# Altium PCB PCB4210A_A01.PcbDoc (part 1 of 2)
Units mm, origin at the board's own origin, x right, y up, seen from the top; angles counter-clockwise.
Board outline 30 x 45 mm, 4 copper layers (Top Layer, Signal Layer 2, Signal Layer 3, Bottom Layer), stack 1.6 mm thick; 78 components, 78 nets, 297 pads, 463 vias.
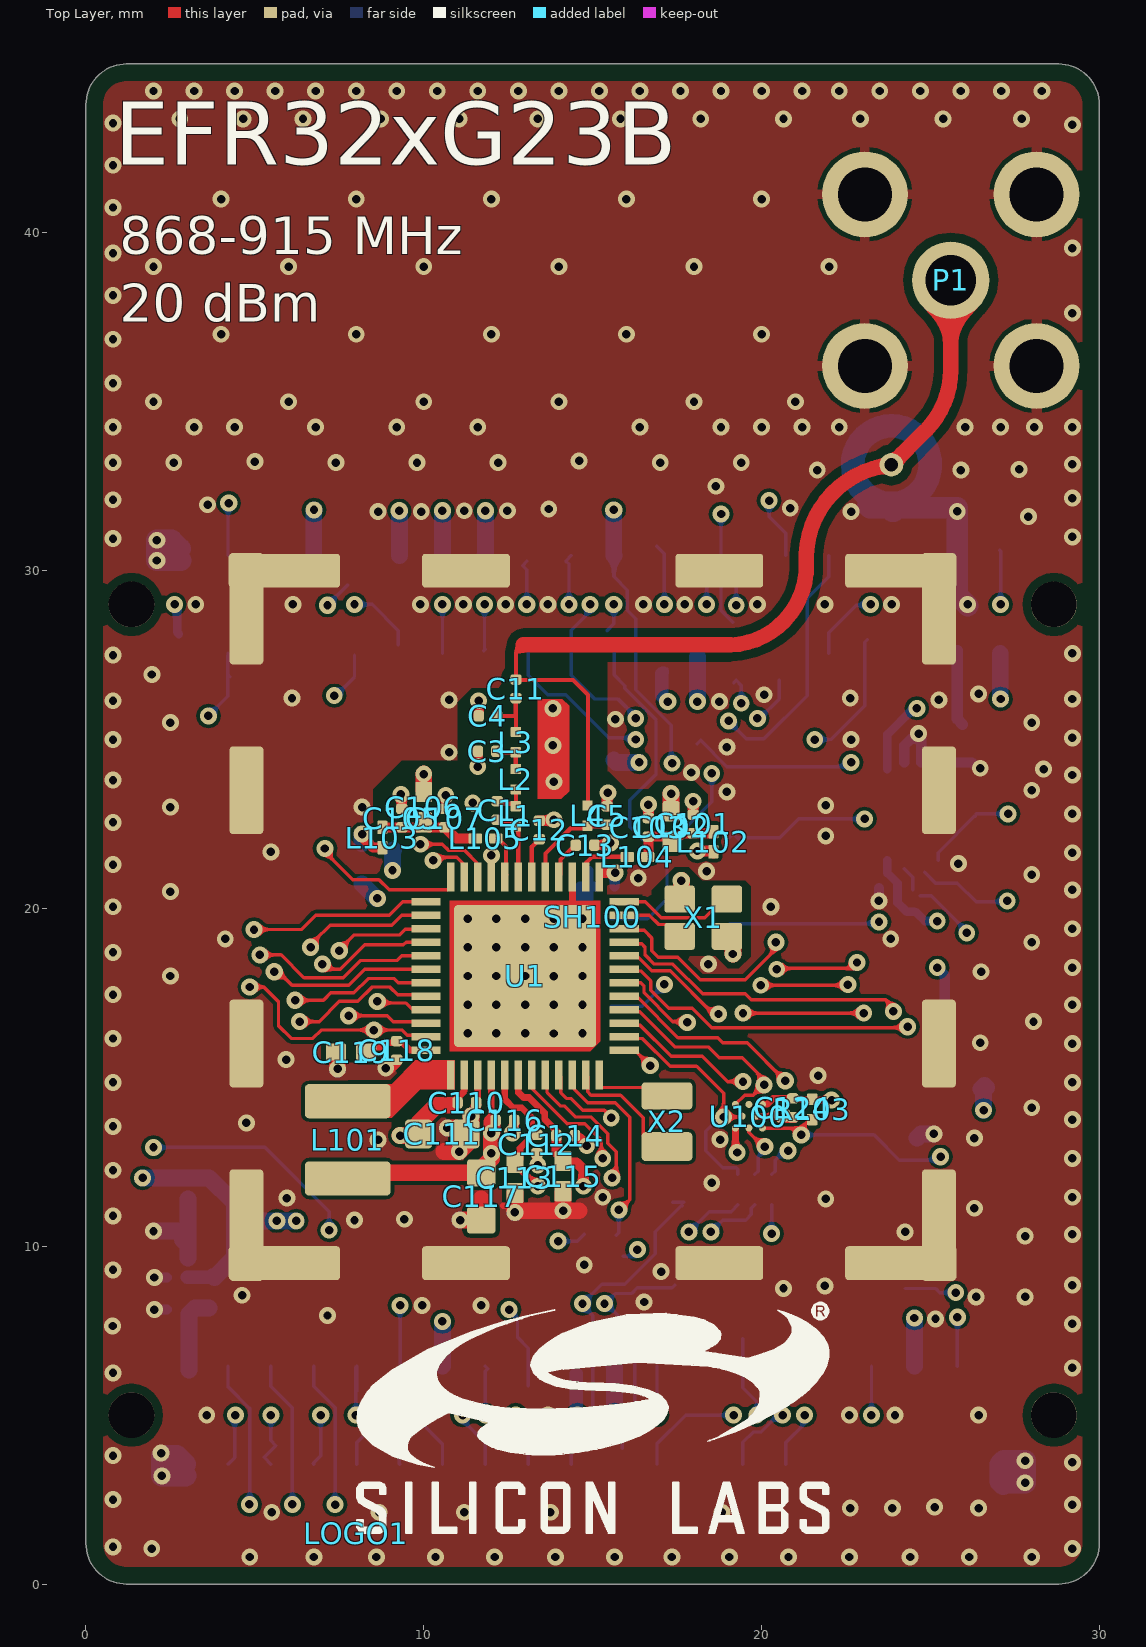
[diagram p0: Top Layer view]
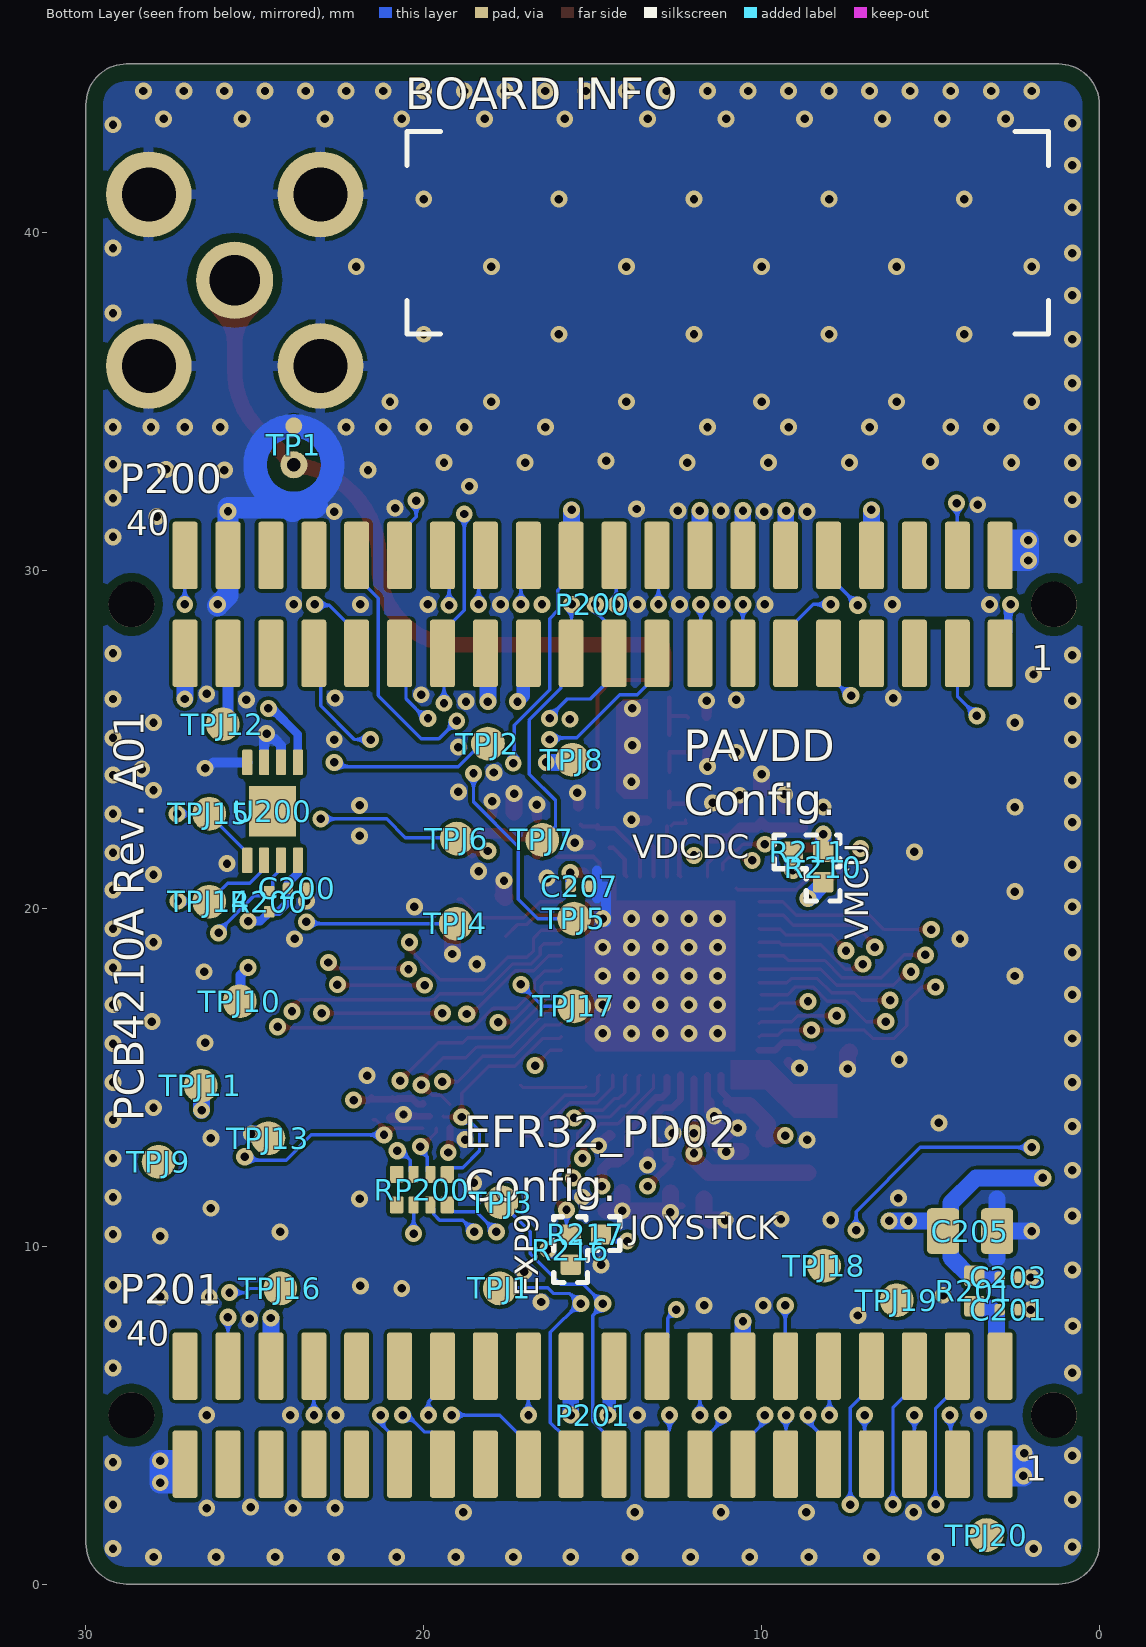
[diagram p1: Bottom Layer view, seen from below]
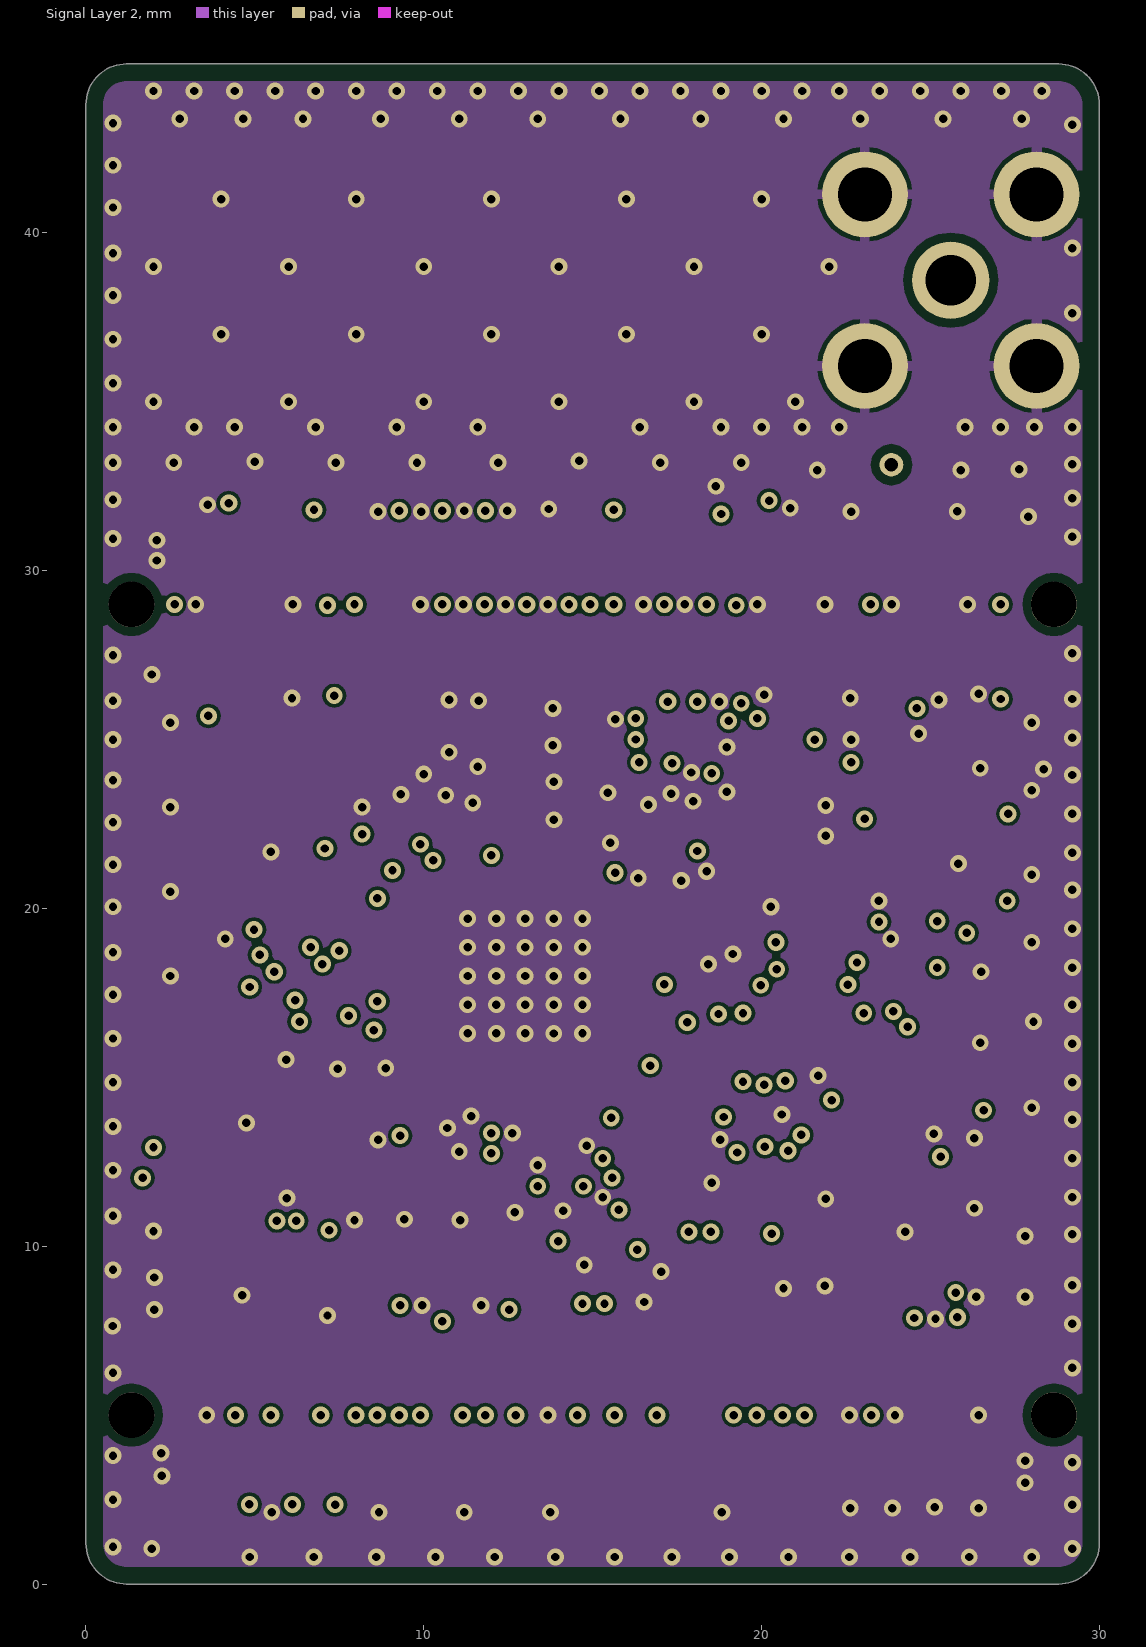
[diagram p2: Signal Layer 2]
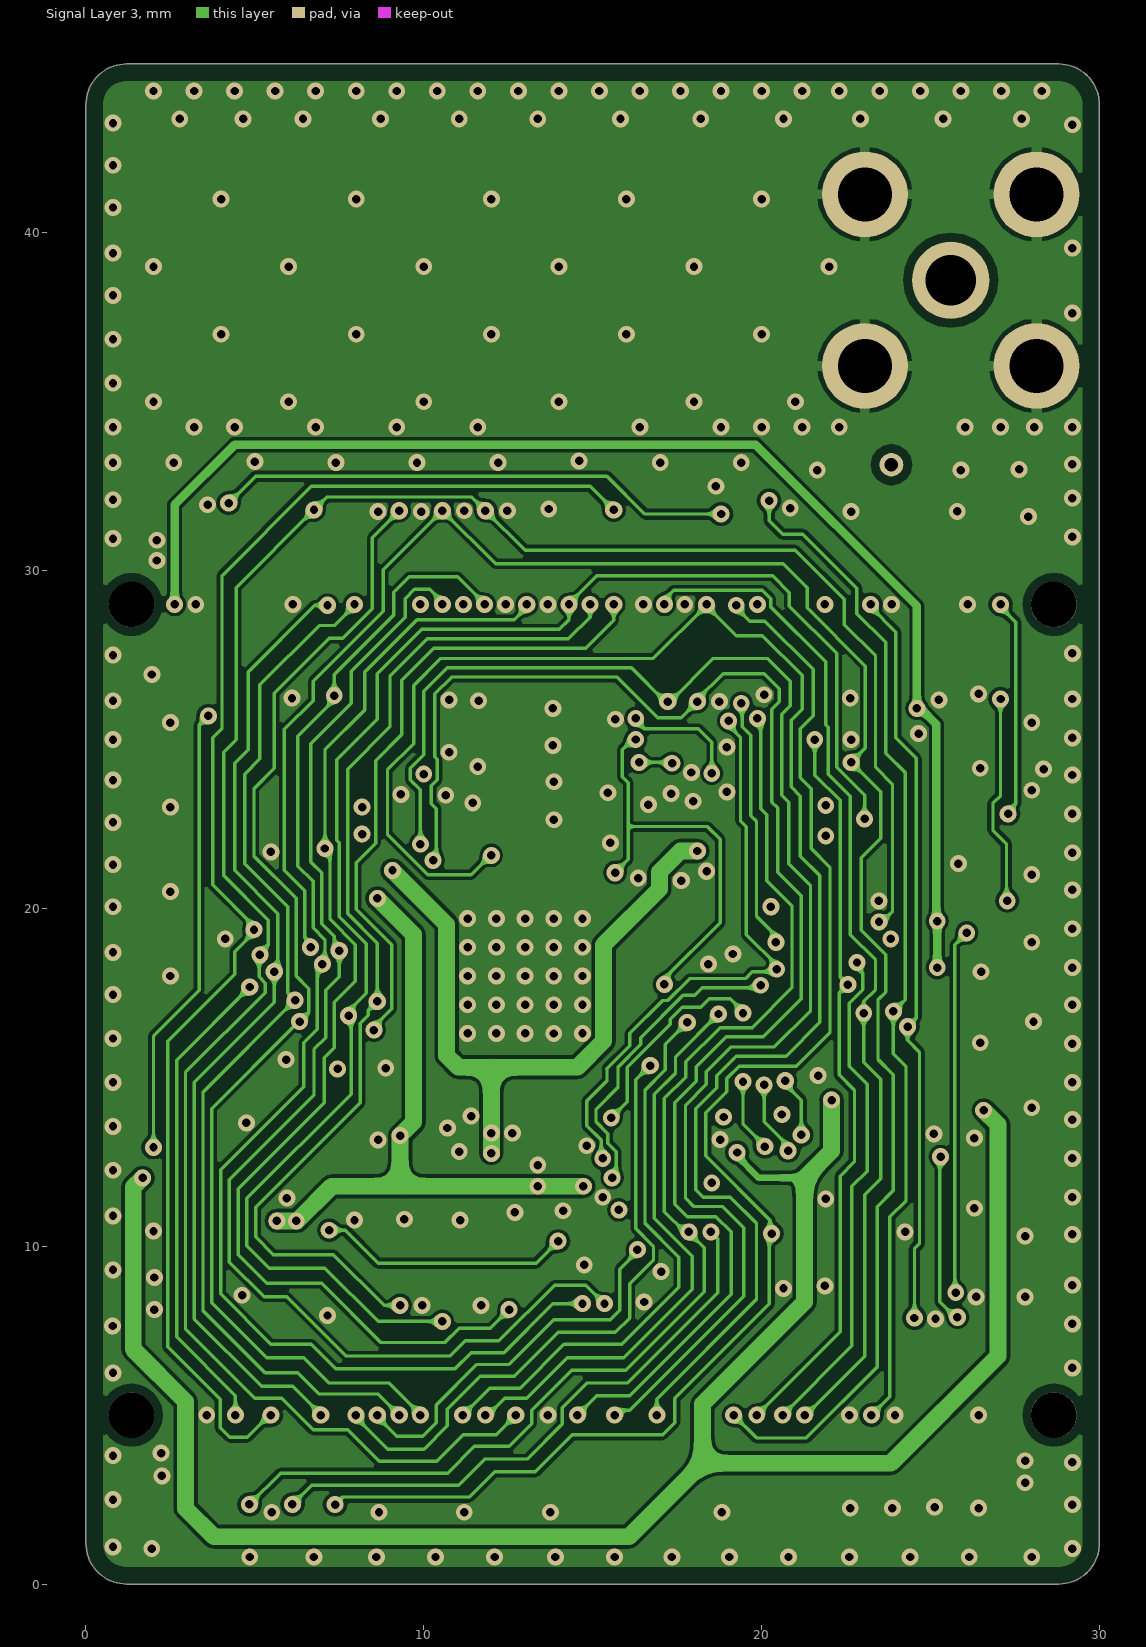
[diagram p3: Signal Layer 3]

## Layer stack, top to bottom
Top Solder: solder mask 0.0102, Solder Resist, Dk 3.5
Top Layer: signal copper 0.035
Dielectric 1: core 0.325, FR-4, Dk 4.2
Signal Layer 2: signal copper 0.018
Dielectric 3: prepreg 0.844, Dk 4.2
Signal Layer 3: signal copper 0.018
Dielectric 2: core 0.325, Dk 4.2
Bottom Layer: signal copper 0.035
Bottom Solder: solder mask 0.0102, Solder Resist, Dk 3.5

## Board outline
0,1.2 0,43.8 cw(c1.2,43.8) 1.2,45 28.8,45 cw(c28.8,43.8) 30,43.8 30,1.2 cw(c28.8,1.2) 28.8,0 1.2,0 cw(c1.2,1.2)

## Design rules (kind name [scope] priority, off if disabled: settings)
AcuteAngle [All] p1: minimum=7.00000000000000E+0001 checktracksonly=FALSE
BoardOutlineClearance [All] p1: gap=0.5
Clearance Clearance_50Ohm [InNetClass('50Ohm') vs InNet('GND')] p1: gap=0.254 except(0.15: Track-SMDPad; 0.2: SMDPad-SMDPad)
Clearance Clearance_to_Holes [InPadClass('NPTH')] p2: gap=0.254
Clearance Clerance_Polygon [InPolygon] p3: gap=0.1
Clearance Clearance_General [All] p4: gap=0.1
HoleToHoleClearance HoleToHoleClearance_ANT1toPAD [Incomponent ('ANT1') vs ISpad] p1: gap=0 allowstackedmicrovias=TRUE
HoleToHoleClearance HoleToHoleClearance_R1toR2_1 [Incomponent ('R1') vs Incomponent ('R2')] p2: gap=0 allowstackedmicrovias=TRUE
HoleToHoleClearance HoleToHoleClearance_U1toVIA_1 [InComponent ('U1') vs IsVia] p3: gap=0 allowstackedmicrovias=TRUE
HoleToHoleClearance [All] p4: gap=0.254 allowstackedmicrovias=TRUE
MinimumSolderMaskSliver [All] p1: minsoldermaskwidth=0.075
PolygonConnect Polygon_VIA_Connect [IsVia] p1: connectstyle=Direct reliefconductorwidth=0.254 reliefentries=4 polygonreliefangle="90 Angle" airgapwidth=0.254
PolygonConnect PolygonConnect_SH100 [InComponent('SH100')] p2: connectstyle=Direct reliefconductorwidth=0.254 reliefentries=4 polygonreliefangle="90 Angle" airgapwidth=0.127
PolygonConnect PolygonConnect_P1 [InComponent('P1')] p3: connectstyle=Relief reliefconductorwidth=0.3 reliefentries=4 polygonreliefangle="90 Angle" airgapwidth=0.127
PolygonConnect [All] p4: connectstyle=NoConnect reliefconductorwidth=0.2 reliefentries=4 polygonreliefangle="90 Angle" airgapwidth=0.125
RoutingVias [All] p1: holewidth=0.3 width=0.65 viastyle="Through Hole" minholewidth=0.25 minwidth=0.5 maxholewidth=1 maxwidth=1.5
ShortCircuit ShortCircuit_ANTtoPAD [InNet('NetAT1_1') vs InNet('GND')] p1: allowed=TRUE
ShortCircuit ShortCircuit_R1toR2_1 [Incomponent ('R1') vs Incomponent ('R2')] p2: allowed=TRUE
ShortCircuit [All] p3: allowed=FALSE
SilkToSilkClearance [All] p1: silktosilkclearance=0.102
SilkToSolderMaskClearance [IsPad] p1: minsilkscreentomaskgap=0.102 clearancetoexposedcopper=TRUE
SolderMaskExpansion [All] p1: expansion=0.051
Width 50ohm [InNet('50R*')] p1: maxlimit=0.457 minlimit=0.124 preferedwidth=0.457
Width [All] p2: maxlimit=5.08 minlimit=0.1 preferedwidth=0.125
25 further rules are at their usual default settings.

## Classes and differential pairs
pad class NPTH: P200-M1 P200-M2 P201-M1 P201-M2
net class 50Ohm: 50R_P1

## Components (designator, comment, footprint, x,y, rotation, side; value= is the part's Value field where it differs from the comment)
C1 "1P9" C0201_L 12.175,22.9 r90 top
C3 "7P2" C0201_L 11.875,24.65 r180 top
C4 "1P3" C0201_L 11.9,25.7 r180 top
C5 "TBD" C0201_L 15.425,22.75 r90 top
C11 "220P" C0201_L 12.73,26.5 r90 top
C12 "1P5" C0201_L 13.425,22.325 r90 top
C13 "1P5" C0201_L 14.775,21.875 r0 top
C101 "TBD" C0201_L 17.975,22.5 r90 top
C102 "1U" C0402_L 17.325,22.425 r90 top
C103 "100P" C0201_L 16.65,22.4 r90 top
C105 "TBD" C0201_L 9.35,22.675 r90 top
C106 "470N" C0402_L 10,23 r90 top
C107 "100P" C0201_L 10.625,22.675 r90 top
C110 "100N" C0201_L 11.275,14.25 r0 top
C111 "10U" C0603_L 10.55,13.325 r0 top
C112 "10N" C0201_L 13.35,13.025 r270 top
C113 "1U" C0402_L 12.7,12.025 r270 top
C114 "100N" C0201_L 14.2,13.275 r0 top
C115 "1U" C0402_L 14.125,12.075 r270 top
C116 "100N" C0201_L 12.4,13.725 r0 top
C117 "4U7" C0603_L 11.7,11.475 r270 top
C118 "100N" C0201_L 9.2,15.8 r270 top
C119 "1U" C0402_L 7.85,15.75 r180 top
C124 "100N" C0201_L 20.925,14.1 r270 top
C200 "100N" C0201_L 23.75,20.6 r180 bottom
C201 "100N" C0201_L 2.675,8.125 r180 bottom
C203 "100N" C0201_L 2.675,9.075 r180 bottom
C205 "10U" C0805_L 3.825,10.45 r180 bottom
C207 "100N" C0201_L 15.375,20.65 r180 bottom
Designator39 "Comment" PCB_SPEC_4_LAYER -68.7,108.2 r0 top
L1 "1N5" COIL_0201_L 12.725,22.725 r90 top
L2 "1N3" COIL_0201_L 12.725,23.825 r90 top
L3 "13N" COIL_0201_L 12.725,24.925 r90 top
L4 "18N" COIL_0201_L 14.85,22.75 r90 top
L101 "2U2" COIL_1008_L 7.75,13.15 r270 top
L102 "BLM03AG700SN1D" COIL_MUR_BLM03_0201 18.575,21.975 r90 top
L103 "0R" COIL_MUR_BLM03_0201 8.775,22.1 r90 top
L104 "0R" COIL_MUR_BLM03_0201 16.325,21.525 r180 top
L105 "BLM03PG330SN1D" COIL_MUR_BLM03_0201 11.825,22.075 r0 top
LOGO1 "Comment" LOGO_SILABS_W14.0 8,1.5 r0 top
P1 "SMA" TE_SMA_1814832_TH_VER 25.6,38.6 r0 top locked
P200 "SOCKET_WCON_2X20_1.27MM_SMD" SAM_SFC-120-T2-D-A-2X20_SNUM 15,29 r0 bottom locked
P201 "SOCKET_WCON_2X20_1.27MM_SMD" SAM_SFC-120-T2-D-A-2X20_SNUM 15,5 r0 bottom locked
R103 "330K" R0201_L 21.5,14.05 r90 top
R200 "10K" R0201_L 24.575,20.2 r270 bottom
R201 "0R" R0402_L 3.7,8.675 r90 bottom
R210 "0R" R0402_L 8.175,21.225 r270 bottom
R211 "0R" R0402_L 8.625,21.675 r180 bottom
R216 "0R" R0402_L 15.65,9.9 r270 bottom
R217 "0R" R0402_L 15.2,10.35 r180 bottom
RP200 "100R" RES_MNR04-8 20.05,11.675 r0 bottom
SH100 "RF_SHIELD_FRAME_36103205S" shield_21x21mm 15,19.75 r180 top locked
TP1 "TP_RF" "TP_INGUN_50_OHM_CLOSED OPENVIA" 23.845,33.135 r0 bottom
TPJ1 "TPJ_SMD" TP_1.0_SMD 17.75,8.75 r90 bottom locked
TPJ2 "TPJ_SMD" TP_1.0_SMD 18.1,24.88 r90 bottom locked
TPJ3 "TPJ_SMD" TP_1.0_SMD 17.7,11.3 r90 bottom locked
TPJ4 "TPJ_SMD" TP_1.0_SMD 19.05,19.55 r90 bottom locked
TPJ5 "TPJ_SMD" TP_1.0_SMD 15.55,19.7 r90 bottom locked
TPJ6 "TPJ_SMD" TP_1.0_SMD 19.02,22.07 r90 bottom locked
TPJ7 "TPJ_SMD" TP_1.0_SMD 16.49,22.03 r90 bottom locked
TPJ8 "TPJ_SMD" TP_1.0_SMD 15.6,24.4 r90 bottom locked
TPJ9 "TPJ_SMD" TP_1.0_SMD 27.85,12.5 r90 bottom locked
TPJ10 "TPJ_SMD" TP_1.0_SMD 25.45,17.25 r90 bottom locked
TPJ11 "TPJ_SMD" TP_1.0_SMD 26.6,14.75 r90 bottom locked
TPJ12 "TPJ_SMD" TP_1.0_SMD 25.95,25.45 r90 bottom locked
TPJ13 "TPJ_SMD" TP_1.0_SMD 24.6,13.2 r90 bottom locked
TPJ14 "TPJ_SMD" TP_1.0_SMD 26.35,20.2 r90 bottom locked
TPJ15 "TPJ_SMD" TP_1.0_SMD 26.35,22.8 r90 bottom locked
TPJ16 "TPJ_SMD" TP_1.0_SMD 24.25,8.75 r90 bottom locked
TPJ17 "TPJ_SMD" TP_1.0_SMD 15.55,17.1 r90 bottom locked
TPJ18 "TPJ_SMD" TP_1.0_SMD 8.15,9.42 r90 bottom locked
TPJ19 "TPJ_SMD" TP_1.0_SMD 6,8.4 r90 bottom locked
TPJ20 "TPJ_SMD" TP_1.0_SMD 3.34,1.45 r90 bottom locked
U1 "EFR32ZG23B020F512GM48" QFN48_M040_6.0X6.0_EP_SL 13,18 r180 top
U100 "MX25R8035F" BGA8_M040_1.24X1.75_WLCSP 19.625,13.85 r270 top
U200 "M24C02" TDFN8_M050_2.0X3.0_EP 24.475,22.875 r270 bottom
X1 "39.000 MHz" KDS_DSX211SH_2016 18.275,19.725 r180 top
X2 "32.768 kHz" X_MCS_CM8V-T1A 17.2,13.7 r270 top

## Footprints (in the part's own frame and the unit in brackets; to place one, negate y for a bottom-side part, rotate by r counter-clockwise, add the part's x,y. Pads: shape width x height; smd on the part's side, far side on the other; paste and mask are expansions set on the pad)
BGA8_M040_1.24X1.75_WLCSP [mm] "BGA, 8 pin. U100"
  round 0.21 smd mask+0.038: A1(-0.35,0.4) A3(0.35,0.4) B2(0,0.2) C1(-0.35,0) C3(0.35,0) D2(0,-0.2) E1(-0.35,-0.4) E3(0.35,-0.4)
  body extent -0.63,-0.89 0.63,0.88, height 0.52
C0201_L [mm] "Capacitor, Chip; 0.60 mm L X 0.30 mm W X 0.33 mm H body"
  rrect52% 0.31x0.34 smd: 1(-0.275,0) 2(0.275,0)
  body extent -0.3,-0.15 0.3,0.15, height 0.3
C0402_L [mm] "Chip Capacitor, 2-Leads, Body 1.0x0.5mm, IPC High Density"
  rrect20% 0.6x0.5 smd mask+0.051: 1(-0.45,0) 2(0.45,0)
  body extent -0.5,-0.25 0.5,0.25, height 0.6
C0603_L [mm] "Capacitor, 0603, High Density (C)"
  rrect25% 0.8x0.85 smd: 1(-0.7,0) 2(0.7,0)
  body extent -0.8,-0.4 0.8,0.4, height 0.95
C0805_L [mm] "Capacitor, 0805"
  rrect25% 0.95x1.35 smd: 1(-0.8,0) 2(0.8,0)
  body extent -1.1,-0.72 1.1,0.72, height 1.45
COIL_0201_L [mm] "JELF243C-0021"
  rrect10% 0.3x0.3 smd: 1(-0.3,0) 2(0.3,0)
  body extent -0.32,-0.17 0.32,0.17, height 0.33
COIL_1008_L [mil] "Chip Inductors, 1008 (2520), Coilcraft (190207)"
  rrect25% 40x100 smd: 1(-45,0) 2(45,0)
  body extent -58,-55 57,55, height 80
COIL_MUR_BLM03_0201 [mm] "COIL_MUR_BLM03_0201"
  rrect25% 0.4x0.3 smd mask+0.051: 1(-0.3,0) 2(0.3,0)
  body extent -0.3,-0.15 0.3,0.15, height 0.95
KDS_DSX211SH_2016 [mm] "Copy of Silabs CE  X_KDS_DSX211SH_2.0X1.65-4"
  rrect20% 0.9x0.8 smd mask+0.051: 1(-0.7,-0.55) 2(0.7,-0.55) 3(0.7,0.55) 4(-0.7,0.55)
  body extent -1.07,-0.87 1.08,0.88, height 0.5
LOGO_SILABS_W14.0 [mm] "LOGO_SILABS_W14.0"
  silkscreen extent 0.03,0 13.99,6.83
PCB_SPEC_4_LAYER [mm]
QFN48_M040_6.0X6.0_EP_SL [mm]
  rrect5% 4.2x4.2 smd paste-4.2 mask-4.2: 0(0,0)
  rect 0.86x0.22 smd paste+0 mask+0.06: 1(-2.935,2.2) 2(-2.935,1.8) 3(-2.935,1.4) 4(-2.935,1) 5(-2.935,0.6) 6(-2.935,0.2) 7(-2.935,-0.2) 8(-2.935,-0.6) 9(-2.935,-1) 10(-2.935,-1.4) 11(-2.935,-1.8) 12(-2.935,-2.2) 25(2.935,-2.2) 26(2.935,-1.8) 27(2.935,-1.4) 28(2.935,-1) 29(2.935,-0.6) 30(2.935,-0.2) 31(2.935,0.2) 32(2.935,0.6) 33(2.935,1) 34(2.935,1.4) 35(2.935,1.8) 36(2.935,2.2)
  rect 0.22x0.86 smd paste+0 mask+0.06: 13(-2.2,-2.935) 14(-1.8,-2.935) 15(-1.4,-2.935) 16(-1,-2.935) 17(-0.6,-2.935) 18(-0.2,-2.935) 19(0.2,-2.935) 20(0.6,-2.935) 21(1,-2.935) 22(1.4,-2.935) 23(1.8,-2.935) 24(2.2,-2.935) 37(2.2,2.935) 38(1.8,2.935) 39(1.4,2.935) 40(1,2.935) 41(0.6,2.935) 42(0.2,2.935) 43(-0.2,2.935) 44(-0.6,2.935) 45(-1,2.935) 46(-1.4,2.935) 47(-1.8,2.935) 48(-2.2,2.935)
  Top Layer pour cut-out: -2.505,-2.31 -2.31,-2.505 2.31,-2.505 2.505,-2.31 2.505,2.309 2.309,2.505 -2.31,2.505 -2.505,2.309
  Top Layer region: 2.225,-2.225 -2.225,-2.225 -2.225,1.925 -1.925,2.225 2.225,2.225
  body extent -3,-3 3,3, height 0.86
R0201_L [mm] "Resistor (Chip2PinSM127P600-8N) (170921)"
  rrect25% 0.34x0.32 smd: 1(-0.3,0) 2(0.3,0)
  body extent -0.32,-0.13 0.32,0.13, height 0.3
R0402_L [mm] "Chip Resistor, 2-Leads, Body 1.0x0.5mm, IPC High Density"
  rrect20% 0.6x0.6 smd mask+0.051: 1(-0.45,0) 2(0.45,0)
  body extent -0.5,-0.25 0.5,0.25, height 0.6
RES_MNR04-8 [mm] "Chip resistor network 8pin"
  rrect20% 0.4x0.5 smd mask+0.051: 1(-0.75,-0.45) 4(0.75,-0.45) 5(0.75,0.45) 8(-0.75,0.45)
  rrect20% 0.3x0.5 smd mask+0.051: 2(-0.25,-0.45) 3(0.25,-0.45) 6(0.25,0.45) 7(-0.25,0.45)
  body extent -1,-0.4 1,0.4, height 0.5
SAM_SFC-120-T2-D-A-2X20_SNUM [mm]
  rrect20% 0.74x2 smd mask+0.05: 1(-12.065,1.45) 2(-12.065,-1.45) 3(-10.795,1.45) 4(-10.795,-1.45) 5(-9.525,1.45) 6(-9.525,-1.45) 7(-8.255,1.45) 8(-8.255,-1.45) 9(-6.985,1.45) 10(-6.985,-1.45) 11(-5.715,1.45) 12(-5.715,-1.45) 13(-4.445,1.45) 14(-4.445,-1.45) 15(-3.175,1.45) 16(-3.175,-1.45) 17(-1.905,1.45) 18(-1.905,-1.45) 19(-0.635,1.45) 20(-0.635,-1.45) 21(0.635,1.45) 22(0.635,-1.45) 23(1.905,1.45) 24(1.905,-1.45) 25(3.175,1.45) 26(3.175,-1.45) 27(4.445,1.45) 28(4.445,-1.45) 29(5.715,1.45) 30(5.715,-1.45) 31(6.985,1.45) 32(6.985,-1.45) 33(8.255,1.45) 34(8.255,-1.45) 35(9.525,1.45) 36(9.525,-1.45) 37(10.795,1.45) 38(10.795,-1.45) 39(12.065,1.45) 40(12.065,-1.45)
  round 1.35 hole 1.35 unplated paste-5.563 mask-5.563: M1(13.652,0) M2(-13.652,0)
  body extent -14.29,-2.1 14.29,2.16, height 4.67
shield_21x21mm [mm]
  rrect20% 1x3.3 smd paste+0 mask+0.05: 1(-10.25,9.125) 1(-10.25,-9.125) 1(10.25,9.125) 1(10.25,-9.125)
  rrect20% 1x2.6 smd paste+0 mask+0.05: 1(-10.25,-3.75) 1(-10.25,3.75) 1(10.25,-3.75) 1(10.25,3.75)
  rrect20% 3.3x1 smd paste+0 mask+0.05: 1(-9.125,10.25) 1(-9.125,-10.25) 1(9.125,10.25) 1(9.125,-10.25)
  rrect20% 2.6x1 smd paste+0 mask+0.05: 1(-3.75,10.25) 1(-3.75,-10.25) 1(3.75,10.25) 1(3.75,-10.25)
  body extent -13,-13 12.99,12.99, height 5.08
TDFN8_M050_2.0X3.0_EP [mm] "TDFN8_M050_2.0x3.0_EP"
  rrect20% 0.75x0.3 smd mask+0.051: 1(-1.45,0.75) 2(-1.45,0.25) 3(-1.45,-0.25) 4(-1.45,-0.75) 5(1.45,-0.75) 6(1.45,-0.25) 7(1.45,0.25) 8(1.45,0.75)
  rect 1.5x1.4 smd mask+0.051: 9(0,0)
  body extent -1.5,-1 1.5,1, height 1.01
TE_SMA_1814832_TH_VER [mm]
  round 2.286 hole 1.5: 1(0,0)
  round 2.54 hole 1.6: 2(-2.54,-2.54) 3(2.54,-2.54) 4(2.54,2.54) 5(-2.54,2.54)
  body extent -3.2,-3.2 3.2,3.2, height 9.5
TP_1.0_SMD [mm] "Test Point, 1.0 mm, SMD"
  round 1 smd paste-0.501: 1(0,0)
  body extent -0.2,-0.2 0.2,0.2, height 0.01
"TP_INGUN_50_OHM_CLOSED OPENVIA" [mm] "TP_INGUN_50_OHM_CLOSED"
  round 0.8 / inner round 0.7 / far side round 0.7 hole 0.4 mask+0: 1(0,0)
  round 0.5 smd paste-0.255 mask-0.41: 2(0,-1.15)
  Top Layer pour cut-out: 0,-0.8 0.4,-0.693 0.693,-0.4 0.8,0 0.693,0.4 0.4,0.693 0,0.8 0,0.8 -0.347,0.721 -0.625,0.499 -0.78,0.178 -0.78,-0.178 -0.625,-0.499 -0.347,-0.721 0,-0.8
  Top Layer lines w0.7: -1.15,0 cw(c0,0) 0,-1.15 cw(c0,0) -1.15,0
X_MCS_CM8V-T1A [mm] "Crystal MCS CM8V-T1A (2 pin)"
  rrect25% 0.8x1.5 smd mask+0.051: 1(-0.75,0)
  rrect25% 0.85x1.5 smd mask+0.051: 2(0.75,0)
  body extent -1,-0.6 1,0.6, height 0.95

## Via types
v1: diameter 0.5, hole 0.25, Top Layer to Bottom Layer, tented both sides, 383 vias
v2: diameter 0.508, hole 0.25, Top Layer to Bottom Layer, tented both sides, 80 vias

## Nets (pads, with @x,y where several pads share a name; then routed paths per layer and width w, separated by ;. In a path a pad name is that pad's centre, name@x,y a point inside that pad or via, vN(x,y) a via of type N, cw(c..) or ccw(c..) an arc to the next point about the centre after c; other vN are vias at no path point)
3V3: C200.1 P200.1 R200.2 TPJ10.1 U200.1 U200.8 | length 46
  Signal Layer 3 w0.254: v1(2.625,29) 2.625,31.95 4.404,33.729 19.821,33.729 24.6,28.95 v1(24.6,25.925) 24.7,25.925 25.177,25.448 25.177,19.625 v1(25.2,19.625) v1(25.2,18.25) 25.175,18.25 v1@25.125,18.2
  Bottom Layer w0.254: v1(2.625,29) 2.625,29.05 2.588,29.012 2.7,28.9 2.7,28.175 P200.1@2.75,28.125 ; U200.8@23.725,21.425 23.725,21.05 24.025,20.75 C200.1@24.025,20.625 ; U200.1@23.725,24.125 23.725,25.152 24.498,25.925 v1(24.6,25.925) ; C200.1@24.025,20.6 24.025,20.175 24.3,19.9 R200.2@24.525,19.9 ; R200.2@24.575,19.885 24.835,19.625 v1(25.2,19.625)
  Bottom Layer w0.305: v1(25.2,18.25) 25.425,18.025 TPJ10.1@25.425,17.1
5V: P200.37 TPJ12.1 | length 2.2
  Bottom Layer w0.33: P200.37@25.795,27.635 P200.37@25.795,27.55 25.795,25.605 TPJ12.1@25.95,25.45
50R_P1: C11.2 L4.2 P1.1 TP1.1 | length 27
  Top Layer w0.125: C11.2@12.73,26.762 14.423,26.762 14.86,26.325 L4.2@14.86,22.987 ; 12.95,27.8 12.73,27.58 C11.2@12.73,26.775 ; C11.2@12.73,26.775 12.725,26.78 C11.2@12.73,26.775
  Top Layer w0.457: 12.95,27.8 19.085,27.8 ccw(c18.992,30.133) 21.318,29.926 21.325,29.933 21.325,30.525 ; 21.326,30.475 cw(c24.079,30.38) TP1.1@23.85,33.125 ; TP1.1@23.845,33.135 24.856,34.146 ccw(c23.06,35.942) 25.6,35.942 P1.1@25.6,38.6
BOARD_ID_SCL: P200.39 TPJ14.1 U200.6 | length 10.5
  Signal Layer 3 w0.1: v1(27.075,26.2) 27.075,23.341 26.85,23.116 26.85,22.316 27.25,21.916 v1@27.25,20.275
  Bottom Layer w0.1: U200.6@24.825,21.075 25.15,20.75 25.8,20.75 TPJ14.1@26.35,20.2 v1@27.375,20.2
  Bottom Layer w0.5: P200.39@27.065,27.55 27.065,26.21 v1(27.075,26.2)
  other v1: 27.275,20.225
BOARD_ID_SDA: P200.40 TPJ15.1 U200.5 | length 10.7
  Signal Layer 3 w0.1: v1@27.075,28.925 27.526,28.474 27.526,23.101 v1@27.3,22.875
  Bottom Layer w0.102: U200.5@25.225,21.425 25.225,21.65 26.3,22.725 TPJ15.1@26.325,22.725 ; TPJ15.1@26.35,22.8 v1(27.3,22.8) ; P200.40@27.05,30.6 27.075,30.575 v1(27.075,29)
BOARD_ID_WP: R200.1 TPJ16.1 U200.7 | length 14.8
  Signal Layer 3 w0.1: v1(25.75,8.625) 25.725,8.65 25.725,18.925 v1(26.075,19.275)
  Bottom Layer w0.1: U200.7@24.225,21.175 24.475,20.925 R200.1@24.475,20.55 ; TPJ16.1@24.25,8.75 25.15,8.75 25.275,8.625 v1(25.75,8.625) ; R200.1@24.7,20.375 25.025,20.375 v1@26.025,19.375
EFR32_PA0: P200.22 P201.5 TPJ8.1 U1.25 | length 59.8
  Top Layer w0.1: v2(4.975,19.375) 6.375,19.375 6.8,19.8 8.975,19.8 9.375,20.2 U1.25@10.065,20.2 U1.25@10.075,20.2
  Signal Layer 3 w0.1: v2(5.475,5) 5.425,5 4.775,4.35 4.25,4.35 3.975,4.625 3.975,5.475 2.425,7.025 2.425,16.075 4.4,18.05 4.4,18.725 4.976,19.301 4.938,19.338 4.902,19.375 v2(4.975,19.375) 4.975,19.475 3.75,20.7 3.75,25.05 4.029,25.329 4.029,29.854 6.675,32.5 14.925,32.5 v2(15.625,31.8) ; v1(16.375,24.325) 17.325,24.325 v1@17.375,24.275
  Bottom Layer w0.1: P201.5@5.475,3.55 5.275,3.75 5.625,4.1 5.475,4.25 v2(5.475,5) ; P200.22@15.635,30.45 15.635,29.815 16.029,29.421 16.029,28.821 16.275,28.575 16.275,26.475 17.325,25.425 17.325,24.35 17.275,24.3 v1(17.35,24.3)
  Bottom Layer w0.5: TPJ8.1@15.625,24.4 15.7,24.325 v1(16.375,24.325) ; v2(15.625,31.8) 15.625,30.46 P200.22@15.635,30.45
EFR32_PA1: P200.14 P201.23 TPJ2.1 U1.26 | length 70.9
  Top Layer w0.1: v2@6.777,19.052 7.233,19.508 9.058,19.508 9.35,19.8 U1.26@10.065,19.8
  Signal Layer 3 w0.1: v2@6.65,19.075 6.55,19.075 6.475,19.15 6.475,20.525 5.875,21.125 5.875,25.3 6.725,26.15 6.725,26.725 8.8,28.8 8.8,30.025 v2(10.55,31.775) 12.125,30.2 20.642,30.2 21.35,29.492 21.35,28.9 23.075,27.175 23.075,24.75 v2(22.65,24.325) 23.525,23.45 23.525,22.075 22.95,21.5 22.95,19.35 23.675,18.625 23.675,17.525 23.447,17.297 23.447,15.528 23.9,15.075 23.9,11.65 23.425,11.175 23.425,6.425 21.325,4.325 19.85,4.325 v1(19.175,5)
  Bottom Layer w0.1: P201.23@16.905,3.55 16.905,4.155 17.75,5 v1(19.175,5) ; TPJ2.1@18.1,24.88 18.196,24.976 18.974,24.199 18.975,24.2 22.777,24.2 22.652,24.325 v2(22.65,24.325)
  Bottom Layer w0.5: v2(10.55,31.775) 10.555,31.77 P200.14@10.555,30.45
  other v2: 6.65,18.85
EFR32_PA2: P200.13 P201.21 TPJ1.1 U1.27 | length 49.1
  Top Layer w0.1: v2(7.5,18.75) v2@7.475,18.75 ; U1.27@10.065,19.4 10.045,19.38 9.45,19.38 9.286,19.215 7.94,19.215 v2@7.475,18.75 ; v2@7.475,18.75 7.438,18.713 7.4,18.75 v2@7.475,18.75
  Signal Layer 3 w0.1: v2@7.35,18.9 7.35,19.175 6.975,19.55 6.975,21.05 6.65,21.375 6.65,24.875 7.85,26.075 7.85,27.025 9.45,28.625 9.45,29.175 9.725,29.45 10.175,29.45 10.55,29.075 v1(10.55,29) ; v2(7.5,18.75) 7.5,17.975 7.1,17.575 7.1,16.175 6.75,15.825 6.75,14.475 4.245,11.97 4.245,9.53 5.275,8.5 5.95,8.5 7.7,6.75 10.775,6.75 11.225,7.2 12.225,7.2 13.875,8.85 14.8,8.85 v1(15.35,8.3) ; v1(15.35,8.3) 15.4,8.25 15.45,8.3 v1(15.35,8.3)
  Bottom Layer w0.1: v1(10.55,29) 10.555,28.995 P200.13@10.555,27.55 ; v1(15.35,8.3) v1@15.375,8.3 ; v1@15.425,8.35 15.475,8.3 v1@15.4,8.3 ; P201.21@15.875,4.025 15.875,4.4 16.25,4.775 16.25,7.45 v1@15.4,8.3 ; TPJ1.1@17.426,8.85 17.35,8.775 16.325,8.775 16.15,8.6 15.675,8.6 v1@15.375,8.3 ; v1@15.375,8.3 v1@15.4,8.3
EFR32_PA3: P200.9 P200.15 P201.19 TPJ3.1 U1.28 | length 56.4
  Top Layer w0.1: v2(7,18.351) 7,18.274 6.926,18.2 7.525,18.2 8.248,18.923 9.399,18.923 9.475,19 U1.28@10.065,19
  Signal Layer 3 w0.1: v2@6.797,18.35 v2@6.849,18.298 ; v2@6.798,18.351 v2@6.849,18.351 ; 6.849,17.476 v2@6.849,18.298 ; 6.85,17.475 6.85,16.425 6.45,16.025 6.45,14.725 3.985,12.26 3.985,8.59 5.475,7.1 6.675,7.1 7.4,6.375 10.925,6.375 11.4,6.85 12.375,6.85 13.825,8.3 v2(14.7,8.3) ; v2(7,18.351) v2@6.951,18.351 ; v2(11.8,29) 11.8,29.025 11,29.825 9.575,29.825 9.113,29.363 9.113,28.688 7.35,26.925 v1(7.35,26.301) 7.35,26.175 6.275,25.1 6.275,21.25 6.725,20.8 6.725,19.425 7.075,19.075 7.075,18.475 v2@6.951,18.351 ; v2@6.849,18.298 v2@6.849,18.351 ; v2@6.849,18.298 6.875,18.272 6.875,18.275 v2@6.951,18.351 ; v2@6.849,18.351 6.849,18.425 v2@6.924,18.351 ; v2@6.849,18.351 v2@6.924,18.351 ; v2@6.924,18.351 6.925,18.351 v2@6.951,18.351
  Bottom Layer w0.1: v1(7.35,26.301) 7.401,26.301 7.95,26.85 P200.9@7.95,27.5 ; P200.15@11.775,27.625 11.825,27.675 11.8,27.7 v2(11.8,29) ; P201.19@14.365,3.55 14.365,4.19 15,4.825 15,7.95 v2@14.7,8.25 ; v2@14.675,8.275 v2@14.7,8.25 ; v2@14.688,8.287 v2(14.7,8.3) ; TPJ3.1@17.375,11.3 TPJ3.1@17.7,11.3 ; TPJ3.1@17.65,11.2 17.625,11.2 16.85,10.425 16.85,9.775 15.95,8.875 15.275,8.875 v2(14.7,8.3) ; v2@14.7,8.25 v2(14.7,8.3)
EFR32_PA4: P200.8 P200.16 P201.17 TPJ4.1 U1.29 | length 80.9
  Top Layer w0.1: v2@5.187,18.625 5.775,18.625 6.454,17.946 7.621,17.946 8.135,18.46 9.21,18.46 9.35,18.6 U1.29@10.065,18.6
  Signal Layer 3 w0.1: v2(12.726,5) 12.15,4.425 11.175,4.425 10.39,3.64 8.685,3.64 7.755,4.57 6.73,4.57 5.8,5.5 5,5.5 2.945,7.555 2.945,15.145 5.304,17.504 5.304,17.792 5.125,17.971 5.125,18.65 5.4,18.925 5.4,19.65 4.075,20.975 4.075,24.625 4.45,25 4.45,29.5 v2(6.75,31.8) 7.129,32.179 11.421,32.179 v2(11.825,31.775) 13,30.6 21,30.6 22.45,29.15 22.45,28.4 23.375,27.475 23.375,24.175 23.875,23.675 23.875,19.9 23.6,19.625 23.575,19.65 23.526,19.601 v1(23.476,19.601)
  Bottom Layer w0.1: v2(12.726,5) 12.726,4.549 13.095,4.18 P201.17@13.095,3.55 ; TPJ4.1@19.05,19.55 23.55,19.55 23.499,19.601 v1(23.476,19.601)
  Bottom Layer w0.5: P200.8@6.745,30.45 6.745,31.795 v2(6.75,31.8) ; P200.16@11.8,30.4 11.825,30.425 v2(11.825,31.775)
  other v2: 5.15,18.626
EFR32_PA5: P200.10 P201.7 U1.30 | length 37
  Top Layer w0.1: v2(5.575,18.126) 5.575,18.2 5.55,18.225 5.575,18.25 6.1,17.725 7.775,17.725 8.25,18.2 9.375,18.2 U1.30@10.065,18.2 U1.30@10.075,18.2
  Signal Layer 3 w0.1: v2@6.725,4.975 6.863,5.112 6.125,5.85 5.2,5.85 3.205,7.845 3.205,14.855 5.575,17.225 5.575,18.126 v2@5.575,18.175 ; v2(7.15,28.975) 6.775,28.975 4.8,27 4.8,24.7 4.4,24.3 4.4,21.125 5.679,19.846 5.679,18.279 v2@5.575,18.175 ; v2@5.575,18.175 5.55,18.15 5.574,18.126 5.449,18.126 5.4,18.175 5.475,18.25 5.575,18.25 v2@5.575,18.175
  Bottom Layer w0.1: P201.7@6.745,3.55 6.725,3.57 6.95,3.795 v2(6.95,5) ; v2(7.15,28.975) P200.10@7.75,29.575
EFR32_PA6: P200.11 P201.11 U1.31 | length 39.1
  Top Layer w0.1: v2(6.193,17.282) 7.032,17.282 7.25,17.5 7.925,17.5 8.35,17.925 9.125,17.925 9.25,17.8 U1.31@10.065,17.8 U1.31@10.075,17.8
  Signal Layer 3 w0.1: v2@7.95,28.975 7.35,28.375 6.9,28.375 5.15,26.625 5.15,24.425 4.7,23.975 4.7,21.325 5.979,20.046 5.979,17.959 5.975,17.954 5.975,17.5 v2(6.193,17.282) 6.185,17.282 3.465,14.561 3.465,8.085 5.3,6.25 6.275,6.25 6.9,5.625 8.65,5.625 v2(9.275,5) ; v2@7.95,28.976 v2(7.95,29) ; v2@9.275,5.025 v2@9.35,5.025
  Bottom Layer w0.1: v2(7.95,29) 8.475,29 9.25,28.225 P200.11@9.25,27.8 ; v2(9.275,5) 9.275,3.56 P201.11@9.285,3.55
EFR32_PA7: P200.12 P201.13 U1.32 | length 42
  Top Layer w0.1: v2(6.325,16.651) 6.901,16.651 7.5,17.25 8.05,17.25 8.475,17.675 9,17.675 9.225,17.45 U1.32@10.015,17.45
  Signal Layer 3 w0.1: 6.126,16.476 3.725,14.075 3.725,8.325 5.35,6.7 6.45,6.7 7.2,5.95 8.975,5.95 9.911,5.014 9.922,5.025 v2@9.975,5.025 ; v2(6.325,16.651) 6.597,16.923 6.597,17.628 6.225,18 6.225,20.3 4.975,21.55 4.975,23.55 5.575,24.15 5.575,26.375 7.2,28 7.6,28 8.475,28.875 8.475,30.975 v2(9.275,31.775)
  Bottom Layer w0.1: v2(9.9,5) 9.9,4.8 10.555,4.145 P201.13@10.555,3.55
  Bottom Layer w0.5: v2(9.275,31.775) 9.285,31.765 P200.12@9.285,30.45
EFR32_PA8: P200.19 P201.12 TPJ5.1 U1.33 | length 49.1
  Top Layer w0.1: v2(8.625,17.25) 8.625,17.375 8.8,17.2 9.475,17.2 9.65,17.025 10.04,17.025 U1.33@10.065,17 U1.33@10.075,17
  Signal Layer 3 w0.1: v2(9.3,8.25) 8.825,8.25 7.325,9.75 5.55,9.75 5.025,10.275 5.025,11.15 8.121,14.246 8.121,16.6 8.358,16.836 8.358,16.983 v2(8.625,17.25) 8.625,18.975 7.75,19.85 7.75,24.125 9,25.375 9,26.875 10.108,27.983 14.283,27.983 14.925,28.625 v2(14.925,29) ; v1@16.25,25.6 16.525,25.325 18.125,25.325 18.527,24.923 v1(18.527,24)
  Bottom Layer w0.1: P201.12@9.285,6.45 9.3,6.465 v2(9.3,8.25) ; v2(14.925,29) 14.925,28.8 14.365,28.24 P200.19@14.365,27.55 14.365,26.902 15.067,26.2 15.75,26.2 16.262,25.688 v1@16.262,25.613 ; TPJ5.1@15.55,19.7 16.625,19.7 17.2,20.275 17.2,21.825 18.527,23.152 v1(18.527,24)
  other v1: 16.275,25.625
EFR32_PA9: P200.20 P201.14 TPJ6.1 U1.34 | length 57.3
  Top Layer w0.1: v2@7.8,16.825 8.925,16.825 9.1,16.65 10.015,16.65 U1.34@10.065,16.6
  Signal Layer 3 w0.1: v2(10.55,7.775) 8.65,7.775 7.075,9.35 5.425,9.35 4.765,10.01 4.765,11.415 7.85,14.5 7.85,16.65 7.75,16.75 7.775,16.775 v2(7.775,16.825) 7.775,16.971 8.3,17.496 8.3,18.95 7.5,19.75 7.5,21.949 7.425,22.024 7.425,24.4 8.625,25.6 8.625,26.95 9.942,28.267 14.017,28.267 14.3,28.55 v2(14.3,29) ; v2@14.25,28.975 15.125,29.85 20.325,29.85 20.825,29.35 20.825,28.95 22.225,27.55 22.225,24.175 23.05,23.35 v1(23.05,22.65)
  Bottom Layer w0.1: v2(14.3,29) P200.20@14.3,30.184 ; P200.20@14.301,30.184 14.2,30.285 P200.20@14.365,30.45 ; TPJ6.1@19.02,22.07 19.162,22.213 TPJ6.1@19.338,22.037 ; TPJ6.1@19.305,22.095 20.545,22.095 21.1,22.65 v1(23.05,22.65)
  Bottom Layer w0.5: v2(10.55,7.775) 10.555,7.77 P201.14@10.555,6.45
EFR32_PA10: P200.21 P201.3 TPJ7.1 U1.35 | length 49
  Top Layer w0.1: v2(4.85,17.675) 5.258,17.675 5.7,17.233 5.7,16.525 6.074,16.151 6.712,16.151 6.962,16.4 8.431,16.4 8.525,16.494 v2(8.525,16.4) 9.365,16.4 9.515,16.25 10.015,16.25 U1.35@10.065,16.2 U1.35@10.075,16.2
  Signal Layer 3 w0.1: v2(4.425,5) 4.425,5.575 2.685,7.315 2.685,15.51 v2(4.85,17.675) ; v2(8.525,16.4) 8.525,16.5 9.05,17.025 9.05,18.925 8,19.975 8,21.35 8.575,21.925 8.575,24.375 9.35,25.15 9.35,26.75 10.3,27.7 14.8,27.7 15.625,28.525 v2(15.625,29) ; v2(4.85,17.675) 4.85,17.775 4.8,17.725 v2(4.85,17.675)
  Bottom Layer w0.1: P201.3@4.205,3.55 4.4,3.745 4.4,4.875 v2@4.3,4.975 ; P200.21@15.425,28.225 15.625,28.425 v2(15.625,29) ; P200.21@15.635,27.55 15.635,26.911 15.95,26.596 15.95,26.517 16.875,25.592 ; TPJ7.1@16.49,22.03 16.1,22.42 16.1,23.2 16.875,23.975 16.875,25.546
EFR32_PB0: P200.18 P201.18 U1.24 | length 43
  Top Layer w0.1: v2(7.075,21.775) 7.025,21.725 7.9,20.85 8.675,20.85 8.975,20.55 10.7,20.55 U1.24@10.75,20.6
  Signal Layer 3 w0.1: v2@7,21.75 7.025,21.775 v2(7.075,21.775) 7.075,24.7 8.25,25.875 8.25,27 9.8,28.55 12.684,28.55 ; v2@7.087,21.588 7.225,21.588 7.225,19.675 7.975,18.925 7.975,17.85 7.35,17.225 7.35,15.875 7.05,15.575 7.05,14.25 4.505,11.705 4.505,9.745 5.35,8.9 6.975,8.9 8.725,7.15 10.625,7.15 11.05,7.575 11.975,7.575 v1(12.525,8.125) ; 12.684,28.55 13,28.866 12.925,28.941 12.984,29 v2(13.05,29)
  Bottom Layer w0.1: v1(12.525,8.125) 12.775,7.875 12.775,7.3 13.095,6.98 P201.18@13.095,6.45 P201.18@13.095,5.87 ; v2(13.05,29) 13.05,30.025 12.925,30.15 P200.18@13.05,30.275
EFR32_PB1: P200.25 P201.20 U1.23 | length 48.5
  Top Layer w0.1: v1@10.31,21.515 10.972,21.515 11.15,21.337 U1.23@11.15,21.15
  Signal Layer 3 w0.1: v1@10.375,21.575 10.375,22.95 10.225,23.1 10.225,23.634 10.4,23.809 10.4,24.409 10.325,24.484 10.325,26.35 10.825,26.85 15.725,26.85 16.929,25.646 17.621,25.646 v2(18.1,26.125) 18.1,26.191 18.859,26.95 20.075,26.95 20.525,26.5 20.525,26.125 20.3,25.9 20.3,23.15 20.475,22.975 20.475,21.075 21.175,20.375 21.175,17.325 20.05,16.2 18.95,16.2 18.062,15.312 18.062,14.887 17.425,14.25 17.425,11.25 17.8,10.875 18.65,10.875 19.1,10.425 19.1,8.575 16.1,5.575 15.125,5.575 v2(14.55,5) ; v2(14.55,5) 14.475,4.925 14.4,5 v2(14.55,5)
  Bottom Layer w0.1: P200.25@18.075,27.475 P200.25@18.1,27.45
  Bottom Layer w0.4: v2@14.515,5 P201.20@14.515,6.225
  Bottom Layer w0.5: v2(18.1,26.125) P200.25@18.1,27.45
  other v1: 10.275,21.425
EFR32_PB2: P200.23 P201.22 U1.22 | length 49.6
  Top Layer w0.1: v1(9.9,21.9) 10.55,21.9 10.735,21.715 11.21,21.715 11.6,21.325 U1.22@11.6,20.935
  Signal Layer 3 w0.1: 9.725,23.684 9.6,23.809 ; v1@9.9,21.959 9.9,23.509 9.6,23.809 ; v2(15.65,5) 15.8,5.15 16.1,5.15 19.475,8.525 19.475,10.55 18.85,11.175 18,11.175 17.75,11.425 17.75,14.175 18.367,14.792 18.367,15.167 19.1,15.9 20.375,15.9 21.45,16.975 21.45,20.675 20.8,21.325 20.8,23.15 20.6,23.35 20.6,25.75 20.85,26 20.85,26.725 20.175,27.4 18.575,27.4 17.3,26.125 v2(17.225,26.125) 17.15,26.125 16.15,27.125 10.7,27.125 10,26.425 10,24.55 9.6,24.15 9.6,23.809
  Bottom Layer w0.1: P200.23@17.05,26.95 P200.23@17.2,27.1
  Bottom Layer w0.4: P200.23@17.05,26.95 17.05,26.3 v2(17.225,26.125)
  Bottom Layer w0.5: P201.22@15.635,6.45 15.65,6.435 v2(15.65,5)
EFR32_PB3: P200.26 P201.24 U1.21 | length 51.9
  Signal Layer 3 w0.1: v1@12.025,21.725 12.025,21.625 11.4,21 10.125,21 8.925,22.2 8.925,24.1 9.7,24.875 9.7,26.6 10.5,27.4 16.8,27.4 18.363,28.962 19.25,28.075 20.025,28.075 21.2,26.9 21.2,25.9 20.875,25.575 20.875,23.6 21.15,23.325 21.15,21.55 21.725,20.975 21.725,16.625 20.725,15.625 19.25,15.625 18.671,15.046 18.671,14.696 18.05,14.075 18.05,11.675 18.275,11.45 19.075,11.45 19.85,10.675 19.85,8.425 16.9,5.475 v2(16.9,5)
  Bottom Layer w0.1: v2(16.9,5) 16.905,5.005 P201.24@16.905,6.45 ; P200.26@18.15,30.125 18.425,29.85 18.375,29.8 v2(18.375,29)
  other v1: 12,21.57
EFR32_PC0: P201.10 U1.1 | length 22
  Top Layer w0.1: U1.1@15.935,15.8 16.25,15.8 v2(16.703,15.347)
  Signal Layer 3 w0.1: v2@7.991,5.188 v2(7.991,5) 7.991,4.934 8.93,3.995 10.008,3.995 10.7,4.687 10.7,5.175 11.675,6.15 12.675,6.15 13.975,7.45 15.675,7.45 16.1,7.875 16.1,8.89 16.8,9.59 16.8,10 16.275,10.525 16.275,14.925 v2@16.7,15.35
  Bottom Layer w0.1: v2(7.991,5) 7.991,6.426 P201.10@8.015,6.45 P201.10@8.015,5.71
EFR32_PC1: RP200.1 U1.2 U100.D2 | length 7.5
  Top Layer w0.1: U1.2@15.935,16.2 15.985,16.15 16.475,16.15 17.3,15.325 18.075,15.325 18.876,14.524 v2(18.876,13.826) U100.D2@19.399,13.826 ; U100.D2@19.4,13.825 U100.D2@19.425,13.85
  Bottom Layer w0.1: v2(18.876,13.826) 18.776,13.826 18.35,13.4 18.35,12.825 18.85,12.325 19.25,12.325 19.3,12.275 RP200.1@19.3,12.125
EFR32_PC2: RP200.2 U1.3 U100.C3 | length 8.3
  Top Layer w0.1: U1.3@15.935,16.6 15.985,16.55 16.4,16.55 17.325,15.625 18.25,15.625 19,14.875 v1(19.45,14.875) ; U100.C3@19.625,13.5 19.625,13.375 v2@20.1,12.9
  Signal Layer 3 w0.1: v1(19.45,14.875) 19.45,13.625 20.1,12.975 v2(20.1,12.95)
  Bottom Layer w0.1: RP200.2@19.8,12.125 19.9,12.225 19.9,12.65 20.176,12.926 20.152,12.95 v2(20.1,12.95)
EFR32_PC3: RP200.3 U1.4 U100.E1 | length 9.4
  Top Layer w0.1: U1.4@15.935,17 16.25,17 16.3,16.95 16.375,16.95 17.425,15.9 18.425,15.9 18.75,15.575 19.425,15.575 20.076,14.924 v2(20.076,14.776) ; U100.E1@19.225,14.2 19.5,14.475 19.75,14.475 v2@20.037,14.762
  Signal Layer 3 w0.1: v2(20.076,14.776) 20.076,13.689 20.784,12.981 v2(20.784,12.828)
  Bottom Layer w0.1: RP200.3@20.3,12.125 20.4,12.225 20.4,12.55 20.731,12.881 v2(20.784,12.828)
EFR32_PC4: P201.38 R103.1 U1.5 U100.A3 | length 20.6
  Top Layer w0.1: U1.5@15.935,17.4 15.985,17.35 16.35,17.35 17.525,16.175 18.7,16.175 18.85,16.025 19.575,16.025 20.663,14.937 20.627,14.901 v2(20.701,14.901) ; U100.A3@20.025,13.5 20.025,13.495 21.16,13.495 21.415,13.75 R103.1@21.5,13.75
  Signal Layer 3 w0.1: v2(20.701,14.901) v2@20.596,14.901 ; v2(21.176,13.296) 21.176,14.32 v2@20.625,14.871 ; v2(25.3,12.65) 25.275,12.625 25.275,8.35 25.75,7.875 25.775,7.9 v2(25.8,7.9) ; v2@20.596,14.901 20.524,14.901 20.494,14.871 v2@20.625,14.871 ; v2@20.596,14.901 v2@20.625,14.871
  Bottom Layer w0.1: v2(21.176,13.296) 23.329,13.296 24.075,12.55 25.2,12.55 v2(25.3,12.65) ; P201.38@25.795,6.45 25.795,7.895 v2(25.8,7.9)
EFR32_PC5: P201.15 U1.6 | length 20.9
  Top Layer w0.1: U1.6@15.935,17.8 16.425,17.8 16.522,17.703 16.522,17.501 17.373,16.65 17.775,16.65 v2(17.8,16.625)
  Signal Layer 3 w0.1: v2(11.15,5) 11.95,5.8 12.85,5.8 14.15,7.1 15.866,7.1 17.55,8.784 17.55,9.675 16.55,10.675 16.55,14.622 17.15,15.222 17.15,15.975 v2(17.8,16.625)
  Bottom Layer w0.1: v2(11.15,5) 11.15,4.85 11.825,4.175 P201.15@11.825,3.55
EFR32_PC6: P200.31 P201.36 U1.7 | length 34.8
  Top Layer w0.1: U1.7@15.935,18.2 15.985,18.15 16.425,18.15 16.722,17.853 16.722,17.584 17.255,17.05 17.95,17.05 18.529,16.471 24.296,16.471 v2(24.325,16.5)
  Signal Layer 3 w0.1: v2@23.226,28.926 23.975,28.178 23.975,25.05 24.575,24.45 24.575,16.75 v2(24.325,16.5) 24.325,16.1 24.675,15.75 24.675,10.075 24.526,9.926 v2(24.526,7.875)
  Bottom Layer w0.1: P200.31@21.985,27.55 21.985,28.16 22.8,28.975 v2@23.2,28.975 ; P201.36@24.525,6.45 P201.36@24.526,6.451
  Bottom Layer w0.5: P201.36@24.526,6.451 v2(24.526,7.875)
  other v2: 23.226,29
EFR32_PC7: P201.16 U1.8 | length 22.2
  Top Layer w0.1: U1.8@15.935,18.6 16.3,18.6 16.745,18.155 17.293,18.155 18.573,16.875 v2(18.725,16.875)
  Signal Layer 3 w0.1: v2(11.825,5) 11.9,5 12.4,5.5 13.05,5.5 14.25,6.7 15.925,6.7 17.95,8.725 17.95,9.7 16.825,10.825 16.825,14.5 17.454,15.129 17.454,15.604 v2(18.725,16.875) ; v2@11.9,4.904 v2@11.948,4.952
  Bottom Layer w0.1: v2(11.825,5) 11.825,6.299 11.9,6.375 P201.16@11.825,6.45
